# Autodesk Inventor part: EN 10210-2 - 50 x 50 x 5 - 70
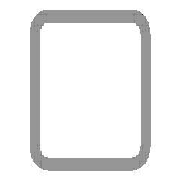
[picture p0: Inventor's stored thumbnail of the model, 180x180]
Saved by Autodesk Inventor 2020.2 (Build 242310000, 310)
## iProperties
IsCustomPart: 1
_CCFamilyMember: 16
_CCFamilyDisplayName: DIN EN 10210-2 (USAS B17.1 quadratisch) - Rohrleitung — In Klammern angegebene Größen wurden aufgehoben
_FrameMemberDoc: Frame Member File
_Version: 15.0.0
_GetPNFromCC: 1
Created: 2019-10
Part Number: EN 10210-2 - 50 x 50 x 5 - 70
Material: Stahl, weich
Description: Rohrleitung
Document SubType Name: Modeling
Standard: DIN
Designer: lutzd
Standard Revision: 2006-07
Standards Organization: DIN
Language: de-DE
Size Designation: 50 x 50 x 5
Categories: <MemberInstance><Categories><Category DisplayName="Profile" InternalName="089c4875-fa83-4c05-b084-43b9cc11f5ed" Mnemonic="GRDR"><CategoryParameter DisplayName="
Stock Number: 50 x 50 x 5
Mass: 479.81 g
Surface Area: 254.441 cm^2
Volume: 61.1222 cm^3
Density: 7.85 g/cm^3
Appearance: Semi-Polished(8)
G_L: 70,000 mm
G_W: 50,000 mm
G_H: 50,000 mm
Dimensions: 50x50x70 mm
Mass: 0,48 kg
DocNumber: ADSK-014292
Folder: .
+32CC1DAF-6088-47DC-917D-6B4B0F2202F8+SCHNITTDETAIL1: Schnittwinkel 90,00 grd
VLT_Material: Stahl, weich
Title: Profil-Bauteil
Author: lutzd
Revision Number: -
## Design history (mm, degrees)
node "Startebene"
node "Endebene"
sketch "Skizze"
  geometry: L1 (-25, -17.5)-(-25, 17.5); L2 (-17.5, 25)-(17.5, 25); L3 (25, 17.5)-(25, -17.5); L4 (17.5, -25)-(-17.5, -25); L5 (-15, 20)-(15, 20); L6 (20, 15)-(20, -15); L7 (15, -20)-(-15, -20); L8 (-20, -15)-(-20, 15); L9 (0, 37.175)-(0, -37.175) reference; L10 (-37.175, 0)-(37.175, 0) reference; A1 r 7.5 centre (-17.5, -17.5) between (-25, -17.5) and (-17.5, -25); A2 r 7.5 centre (-17.5, 17.5) between (-17.5, 25) and (-25, 17.5); A3 r 7.5 centre (17.5, 17.5) between (25, 17.5) and (17.5, 25); A4 r 7.5 centre (17.5, -17.5) between (17.5, -25) and (25, -17.5); A5 r 5 centre (-15, -15) between (-20, -15) and (-15, -20); A6 r 5 centre (-15, 15) between (-15, 20) and (-20, 15); A7 r 5 centre (15, 15) between (20, 15) and (15, 20); A8 r 5 centre (15, -15) between (15, -20) and (20, -15)
  constraints: 16 end point, 16 point on circle, 16 tangent, 8 centre point, 6 equal radius, 4 parallel, 2 perpendicular, 2 other
  dimensions: "d7" = 7.5 radius of A1 (= G_IR); "d10" = 50 distance between parallel lines of L2 L4 (= G_H); "d11" = 50 distance between parallel lines of L1 L3 (= G_W); "d12" = 5 distance between parallel lines of L3 L6 (= G_T); "d15" = 25 distance between parallel lines of L2 L10 (= 0.5 x d10); "d16" = 25 distance between parallel lines of L9 L3 (= 0.5 x d11); "d19" = 5 radius of A5 (= G_T); "d20" = 5 distance between parallel lines of L4 L7 (= G_T)
extrude "Körper" new body sketch "Skizze" stored distance "d3" = 70 (= G_L); taper "d4" = 0 deg
node "Driven Length"
  sketch "Sketch3"
    geometry: L1 (0, 0)-(10, 0) reference
    constraints: 2 end point, 1 horizontal
  workplane "Work Plane3"
  sketch "Sketch4"
    geometry: L1 (-2, 25)-(12, 25) reference; L2 (-2, 95)-(12, 95) reference
    dimensions: "d18" = 70 distance between parallel lines of L1 L2 (derived)
workplane "Arbeitsebene4"
feature "Trennen1"
body "Solid1"
other parameters: "G_W" = 50 [user parameter; used in 1 equation term], "G_H" = 50 [user parameter; used in 1 equation term], "G_T" = 5 [user parameter; used in 3 equation terms], "G_IR" = 7.5 [user parameter; used in 1 equation term], "G_L" = 70 (= d18) [user parameter; used in 1 equation term], "G_OFFSET_START" = -25 [user parameter; used in 1 equation term], "G_OFFSET_END" = 0 [user parameter; used in 1 equation term], "d13" = 25 (= -G_OFFSET_START), "d14" = 95 (= G_OFFSET_END + B_L), "B_L" = 95 [user parameter; used in 1 equation term], "d17" = 90 deg
